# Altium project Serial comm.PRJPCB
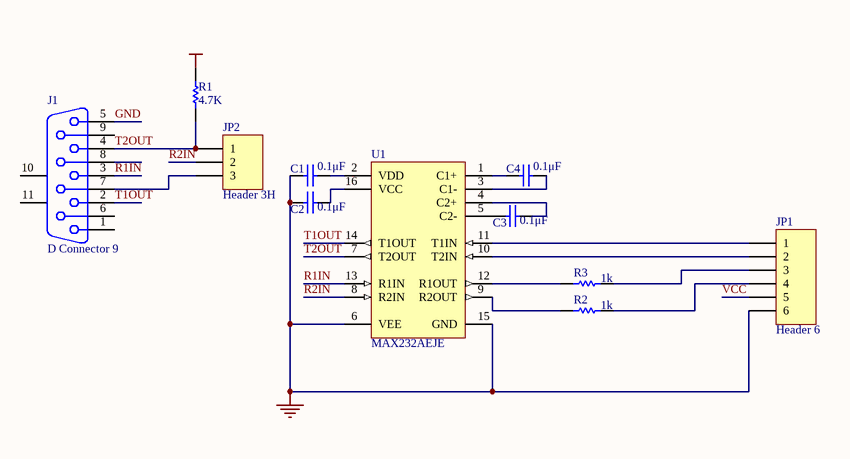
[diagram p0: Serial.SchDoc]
1 sheet, 11 parts. Net scope: global (net labels, ports and power ports of the same name join across sheets).
Board file: serial comm.PCBDOC

## Sheet Serial.SchDoc
size B

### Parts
C1  0.1μF  [RAD-0.3]
C2  0.1μF  [RAD-0.3]
C3  0.1μF  [RAD-0.3]
C4  0.1μF  [RAD-0.3]
J1  D Connector 9  [DSUB1.385-2H9]
JP1  Header 6  [HDR1X6]
JP2  Header 3H  [HDR1X3H]
R1  4.7K  [AXIAL-0.3]
R2  1k  [AXIAL-0.3]
R3  1k  [AXIAL-0.3]
U1  MAX232AEJE  [DIP-16/D21.7]

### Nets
GND: C1.1 C2.1 J1.5 JP1.6 U1.6(VEE) U1.15(GND)
VCC: JP1.5 R1.2
R1IN: J1.3 U1.13(R1IN)
R2IN: JP2.2 U1.8(R2IN)
T1OUT: J1.2 U1.14(T1OUT)
T2OUT: J1.4 JP2.1 R1.1 U1.7(T2OUT)
NetC1_2: C1.2 U1.2(VDD)
NetC2_2: C2.2 U1.16(VCC)
NetC3_1: C3.1 U1.5(C2-)
NetC3_2: C3.2 U1.4(C2+)
NetC4_1: C4.1 U1.1(C1+)
NetC4_2: C4.2 U1.3(C1-)
NetJ1_7: J1.7 JP2.3
NetJP1_1: JP1.1 U1.11(T1IN)
NetJP1_2: JP1.2 U1.10(T2IN)
NetJP1_3: JP1.3 R3.1
NetJP1_4: JP1.4 R2.1
NetR2_2: R2.2 U1.9(R2OUT)
NetR3_2: R3.2 U1.12(R1OUT)

Not connected (* = marked no-connect by the designer): J1 1 6 8 9 10(MH1) 11(MH2)

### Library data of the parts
C1 = Cap: Capacitor; Manufacturer: Generic Components; Class I: Passive; Value: 100pF
C2-C4 = Cap: Capacitor; Manufacturer: Generic Components; Class I: Passive
J1 = D Connector 9: Receptacle Assembly, 9 Position, Right Angle; Manufacturer: Generic Components; Package Information: Latest Revision: O; Positions: 9
JP1 = Header 6: Header, 6-Pin; Manufacturer: Generic Components; Class I: Connector
JP2 = Header 3H: Header, 3-Pin,  Right Angle; Manufacturer: Generic Components; Class I: Connector
R1 = Res1: Resistor; Manufacturer: Generic Components; Class I: Passive; Value: 1K
R2 R3 = Res1: Resistor; Manufacturer: Generic Components; Class I: Passive
U1 = MAX232AEJE: +5V Powered, Multi-Channel RS-232 Driver/Receiver; Manufacturer: Maxim; Class I: Communication; Class II: Transceiver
